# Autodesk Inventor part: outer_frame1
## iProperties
Shininess: 64.0
Length Units: 11269
Angle Units: 11279
Time Units: 11290
Mass Units: 11283
Length Display Precision: 3
Angle Display Precision: 2
Compacted: True
Part Number: outer_frame1
Document SubType Name: Modeling
Created: 2003-02
Material: Standard
Designer: hofer_a
Density: 0.0
Volumn: 0.0
Area: 0.0
PropertySet Name: Model Information
Control State: 0
Master: False
Checked Out: False
Author: hofer_a
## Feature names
1. Extrusion3
2. Fillet1
3. Chamfer3
4. Hole5
5. Chamfer4
6. Fillet2
7. Extrusion9
8. Hole6
